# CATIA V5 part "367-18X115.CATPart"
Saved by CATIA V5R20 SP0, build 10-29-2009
Part number: 367-18X115
Definition: NONE
Nomenclature: 367-18X115
Source: Unknown
Description: 367-18X115
Bounding box of the stored display mesh (mm): x 0 to 115, y -14 to 14, z -14 to 14
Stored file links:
  C:\Users\Utente\Desktop\IO LAVORO\3D X SITO CF\X SITO\PLASTICA\3D files 367\367-18X115.CATPart
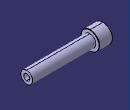
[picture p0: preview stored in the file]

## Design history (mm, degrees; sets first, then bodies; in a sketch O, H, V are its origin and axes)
Body1 "367-18X115" (main body)
  Solid1: solid without history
